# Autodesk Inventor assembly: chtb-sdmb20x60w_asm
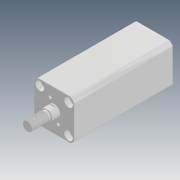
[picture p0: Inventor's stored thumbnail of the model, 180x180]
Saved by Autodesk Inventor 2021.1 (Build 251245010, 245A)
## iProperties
Company: Microsoft
Created: 2018-05
Part Number: chtb-sdmb20x60w_asm
Description: STEP AP214
Document SubType Name: Assembly
Designer: user
Title: chtb-sdmb20x60w_asm.STEP
Author: Windows
Revision Number: ÈÎºÎ
Sending System: SolidWorks 2015
Preprocessor: SwSTEP 2.0
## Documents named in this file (4)
- D:\Vault_2016\Projekty\Clamptek\Hydraulic\CHTB\CHTB-20\Inventor\CHTB-SDMB20x60W\chtb-sdmb20x60w_asm.iam
- D:\Vault_2016\Projekty\Clamptek\Hydraulic\CHTB\CHTB-20\Inventor\CHTB-SDMB20x60W\CHTB-SDMB20X60NBT.ipt
- D:\Vault_2016\Projekty\Clamptek\Hydraulic\CHTB\CHTB-20\Inventor\CHTB-SDMB20x60W\CHTB-SDMB20X60WHSG.ipt
- D:\Vault_2016\Projekty\Clamptek\Hydraulic\CHTB\CHTB-20\Inventor\CHTB-SDMB20x60W\QG_3.ipt
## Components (3 placed, 3 different names)
1. CHTB-SDMB20X60NBT_1
2. CHTB-SDMB20X60WHSG_2
3. QG_3_3
